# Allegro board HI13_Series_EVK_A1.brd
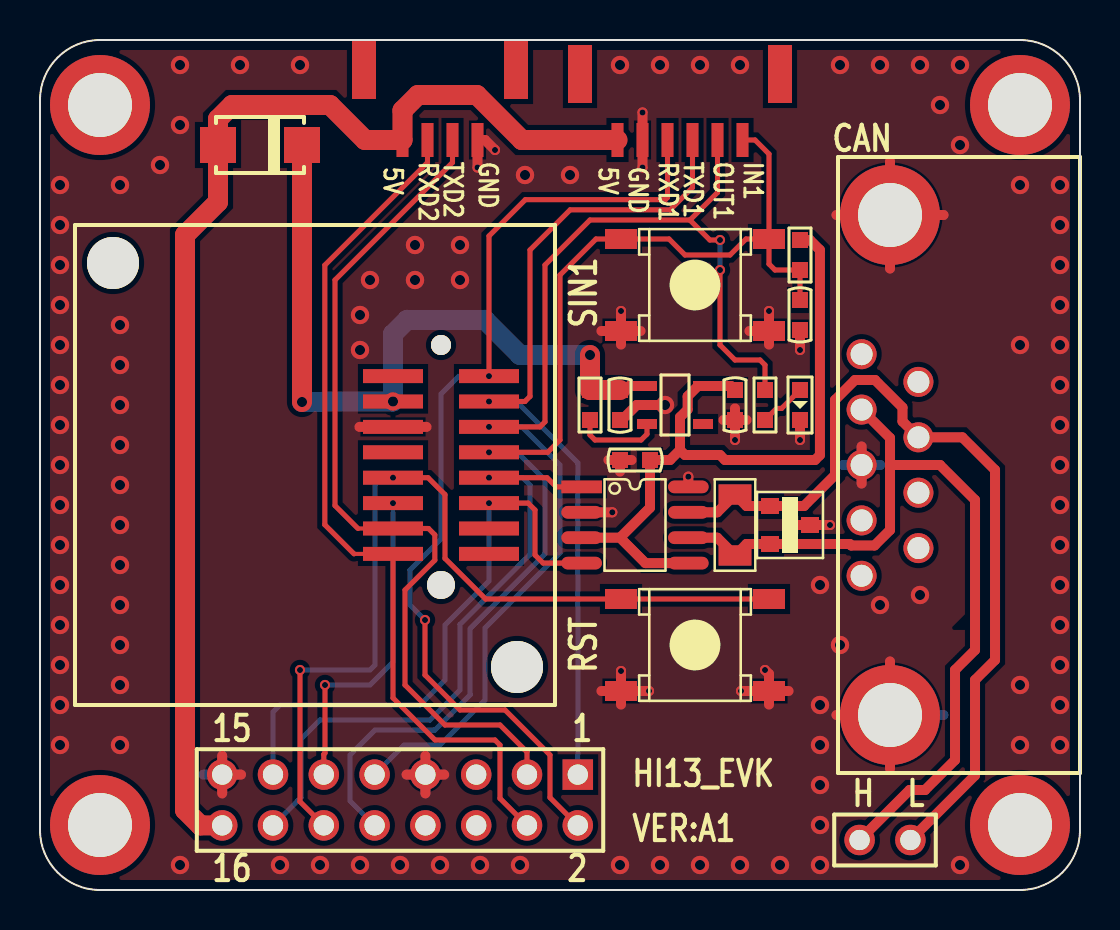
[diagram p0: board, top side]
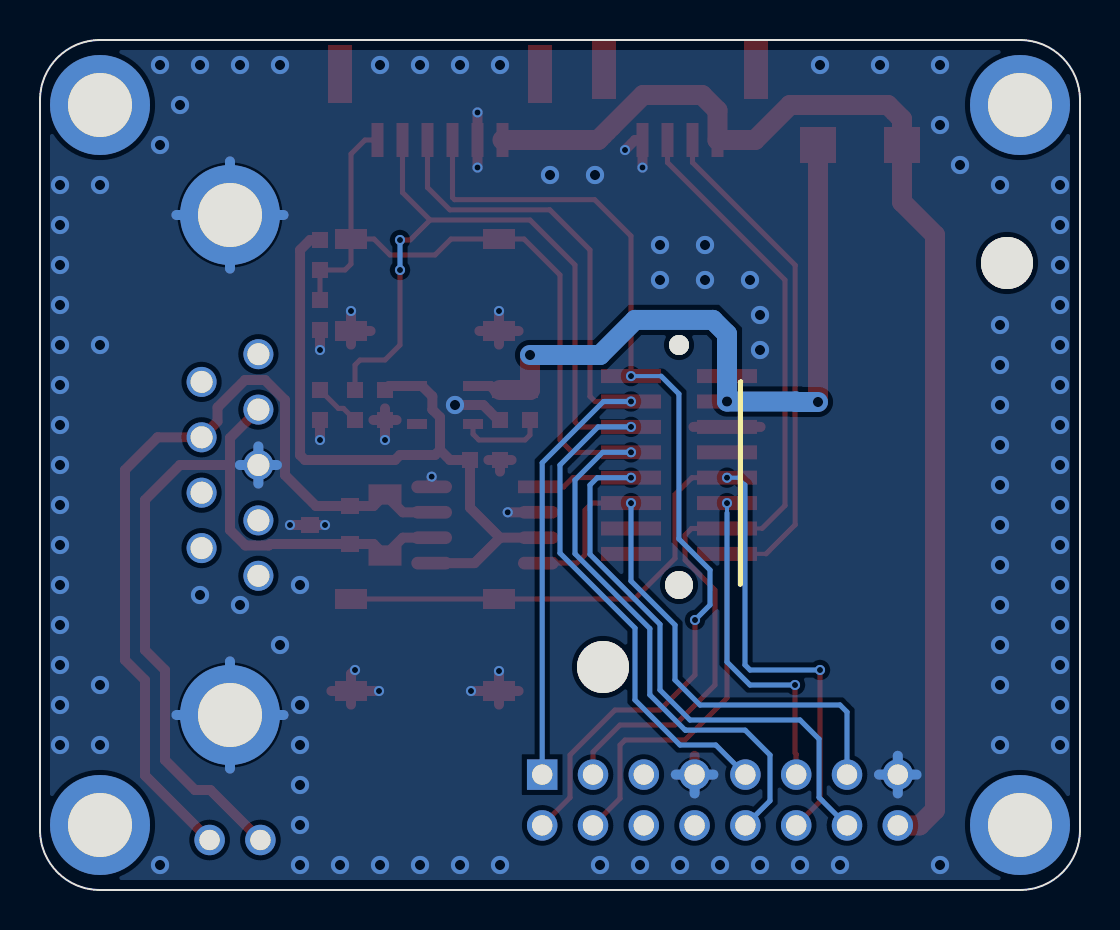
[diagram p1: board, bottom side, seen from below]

Outline 52 x 42.5 mm; copper layers: TOP, BOTTOM. Coordinates in mm from the lower left corner of the outline.
Outline path: 0,39.5 0,3 arc(0.88,0.88) 3,0 49,0 arc(51.12,0.88) 52,3 52,39.5 arc(51.12,41.62) 49,42.5 3,42.5 arc(0.88,41.62) 0,39.5

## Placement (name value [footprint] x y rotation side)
C1  0.1uF  [C0603]  29 24.25 270 top
C2  1uF  [C0603]  34.75 24.25 90 top
C3  0.1uF  [C0603]  38 28.75 90 top
C4  0.1uF  [C0603]  29.75 21.5 0 top
D1  1N4007  [DO-214AC]  11 37.25 180 top
D3  SM24CANB-02HTG  [SOT23-3-0_95]  37.5 18.25 270 top
D4  RED  [LED0603]  38 24.25 270 top
H1  HOLE  [HOLE-3-MM]  3 39.25 0 top
H2  HOLE  [HOLE-3-MM]  3 3.25 0 top
H3  HOLE  [HOLE-3-MM]  49 3.25 0 top
H4  HOLE  [HOLE-3-MM]  49 39.25 0 top
J1  CON6  [A1257WV-S-6P]  32 37.5 0 top
J2  CON4  [GH1X4-1_25MM_90]  20 37.5 0 top
J3  CONN PCB 8x2  [HEADER2X8-2_54MM]  18 4.5 180 top
J5  DB9  [DB9_FEMALE]  42.5 21.25 270 top
J6  CONN PCB 2  [HEADER1X2-2_54MM]  42.25 2.5 180 top
K1  Button2  [BUTTON_6X6]  32.75 12.25 270 top
K2  Button2  [BUTTON_6X6]  32.75 30.25 270 top
R1  4.7K  [R0603]  27.5 24.25 90 top
R2  4.7K  [R0603]  38 31.75 90 top
R3  120R  [R1206]  34.75 18.25 270 top
R5  510R  [R0603]  36.25 24.25 270 top
U1  RS3219-3.3YF5  [SOT23-5-0_95]  31.75 24.25 270 top
U2  SIT65HVD234DR  [SOP8]  29.75 18.25 0 top
U3  HI13  [HI13_UCX]  13.75 21.25 0 top

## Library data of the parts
C1-C4 = Capacity_Nonpolarity
D1 = diode
D3 = BAT54A/SOT
D4 = LED
H1-H4 = HOLE
J1 = CON6
J2 = CON4
J3 = CONN PCB 8x2
J5 = CONN_DB9M_MTGTABS
J6 = CONN PCB 2
K1 K2 = Button2
R1-R3 R5 = Res
U1 = XC6210
U2 = SN65HVD234-Q1
U3 = hi13

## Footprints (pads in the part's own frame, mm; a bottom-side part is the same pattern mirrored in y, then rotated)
A1257WV-S-6P
  rect 1.2x2.9 smd: (-5,3.3) (5,3.3)
  rect 0.6x1.7 smd: 1(-3.125,0) 2(-1.875,0) 3(-0.625,0) 4(0.625,0) 5(1.875,0) 6(3.125,0)
BUTTON_6X6
  rect 1x1.6 smd: 1(2.3,3.7) 2(2.3,-3.7) 3(-2.3,-3.7) 4(-2.3,3.7)
C0603
  rect 0.8x0.8 smd: 1(-0.75,0) 2(0.75,0)
DB9_FEMALE
  round 1.5 hole 1.1: 1(-5.54,-1.42) 2(-2.77,-1.42) 3(0,-1.42) 4(2.77,-1.42) 5(5.54,-1.42) 6(-4.155,1.42) 7(-1.385,1.42) 8(1.385,1.42) 9(4.155,1.42)
  round 5 hole 3.2: M1(12.5,0) M2(-12.5,0)
DO-214AC
  rect 1.8x1.8 smd: 1(2.1,0) 2(-2.1,0)
GH1X4-1_25MM_90
  rect 1.2x2.9 smd: (-3.8,3.5) (3.8,3.5)
  rect 0.6x1.7 smd: 1(-1.875,0) 2(-0.625,0) 3(0.625,0) 4(1.875,0)
HEADER1X2-2_54MM
  round 1.524 hole 1.016: 1(-1.27,0) 2(1.27,0)
HEADER2X8-2_54MM
  rect 1.524x1.524 hole 1.016: 1(-8.89,-1.27)
  round 1.524 hole 1.016: 2(-8.89,1.27) 3(-6.35,-1.27) 4(-6.35,1.27) 5(-3.81,-1.27) 6(-3.81,1.27) 7(-1.27,-1.27) 8(-1.27,1.27) 9(1.27,-1.27) 10(1.27,1.27) 11(3.81,-1.27) 12(3.81,1.27) 13(6.35,-1.27) 14(6.35,1.27) 15(8.89,-1.27) 16(8.89,1.27)
HI13_UCX
  round 2.6 hole 2.6 unplated: (-10.1,10.1) (10.1,-10.1)
  round 1 hole 1 unplated: (6.3,6)
  round 1.4 hole 1.4 unplated: (6.3,-6)
  rect 3x0.7 smd: 1(8.7,-4.445) 2(3.9,-4.445) 3(8.7,-3.175) 4(3.9,-3.175) 5(8.7,-1.905) 6(3.9,-1.905) 7(8.7,-0.635) 8(3.9,-0.635) 9(8.7,0.635) 10(3.9,0.635) 11(8.7,1.905) 12(3.9,1.905) 13(8.7,3.175) 14(3.9,3.175) 15(8.7,4.445) 16(3.9,4.445)
HOLE-3-MM
  round 5 hole 3.2: 1(0,0)
LED0603
  rect 0.8x0.8 smd: 1(-0.75,0) 2(0.75,0)
R0603
  rect 0.8x0.8 smd: 1(-0.75,0) 2(0.75,0)
R1206
  rect 1.016x1.651 smd: 1(-1.524,0) 2(1.524,0)
SOP8
  rect 2.032x0.635 smd: 1(-2.667,1.905)
  oval 2.032x0.635 smd: 2(-2.667,0.635) 3(-2.667,-0.635) 4(-2.667,-1.905) 5(2.667,-1.905) 6(2.667,-0.635) 7(2.667,0.635) 8(2.667,1.905)
SOT23-3-0_95
  rect 0.8x0.9 smd: 1(-0.95,-1) 2(0.95,-1) 3(0,1)
SOT23-5-0_95
  rect 0.5x1 smd: 1(-0.95,-1.4) 2(0,-1.4) 3(0.95,-1.4) 4(0.95,1.4) 5(-0.95,1.4)

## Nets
GND: C1.2 C2.1 C3.1 C4.1 D3.3 D4.2(-) J1.2 J2.4 J3.7(12) J3.15(16) J5.3 J5.M1 J5.M2 K1.1 K1.2 K2.1 K2.2 U1.2(VSS) U2.2(GND) U2.8(RS) U3.12(GND)
VCC: D1.1(P) J1.1 J2.1 J3.16(8)
CAN_RX: J3.13(15) U2.4(RXD) U3.5(CAN_RX)
CAN_TX: J3.14(7) U2.1(TXD) U3.7(CAN_TX)
CANH: D3.1 J5.7 J6.1 R3.1 U2.7(CAN-H)
CANL: D3.2 J5.2 J6.2 R3.2 U2.6(CAN-L)
DP3V3: C2.2 C4.2 R2.2 U1.5(VOUT) U2.3(VCC) U2.5(EN)
DP5V: C1.1 D1.2(N) R1.2 U1.1(VIN) U3.14(VDD)
IO5: J3.11(14) U3.6(IO5)
NRST: J3.12(6) K1.3 K1.4 U3.8(NRST)
RXD1: J1.3 J3.2(1) U3.15(RXD1)
RXD2: J2.2 J3.4(2) U3.2(RXD2)
SYNC_IN: C3.2 J1.6 J3.10(5) K2.3 K2.4 R2.1 U3.9(SYNC_IN1)
SYNC_OUT: J1.5 J3.9(13) R5.1 U3.11(SYNC_OUT1)
TXD1: J1.4 J3.1(9) U3.13(TXD1)
TXD2: J2.3 J3.3(10) U3.4(TXD2)
N1746824: D4.1(+) R5.2
N1748528: R1.1 U1.3(CE)

Pads without a net: H1 1; H2 1; H3 1; H4 1; J3 5 6 8; J5 1 4 5 6 8 9; U1 4; U3 1 3 10 16

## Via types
v1: diameter 0.508, hole 0.305, TOP to BOTTOM, 30 vias
v2: diameter 0.914, hole 0.508, TOP to BOTTOM, 97 vias

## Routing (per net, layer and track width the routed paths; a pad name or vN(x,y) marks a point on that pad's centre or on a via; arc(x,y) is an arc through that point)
GND: length 94.8
  TOP w0.5: v1(22.75,37) 22.25,37.5 J2.4 v1(21.88,36.12) ; 39.82,33.75 J5.M2 ; J5.M2 45.18,33.75 ; J5.M2 42.5,31.07 ; J5.M2 42.5,36.43 ; 41.08,22.18 J5.3 41.08,20.32 ; U2.8 v1(32.42,20.67) ; 42.5,6.07 J5.M1 ; J5.M1 39.82,8.75 ; J5.M1 42.5,11.43 ; 34.17,23.5 C2.1 ; C2.1 34.75,24.08 ; C2.1 v1(34.75,22.5) ; C2.1 35.33,23.5 ; U2.2 v1(28.62,18.88) ; v2(31.25,24.25) U1.2 29.84,24.25 29.09,23.5 C1.2 ; D4.2 v1(38,22.5) ; C3.1 v1(38,27) ; 28.42,21.5 C4.1 ; C4.1 29.58,21.5 ; C4.1 29,20.92 ; J3.15 10.05,5.77 ; J3.15 9.11,4.83 ; J3.15 9.11,6.71 ; 18.33,5.77 J3.7 ; J3.7 20.21,5.77 ; J3.7 19.27,6.71 ; J3.7 19.27,4.83 ; K1.1 v1(35.05,9.95) ; K1.1 36.45,10.8 v1(36.25,11) ; K1.1 36.45,9.27 ; K1.1 37.43,9.95 ; 29.05,9.27 K1.2 ; K1.2 v1(30.45,9.95) ; K1.2 28.07,9.95 ; K1.2 v1(29.05,10.95) ; 15.97,23.16 U3.12 19.33,23.16 ; K2.1 v1(36.45,28.95) ; K2.1 36.45,27.27 ; K2.1 35.47,27.95 ; K2.2 v1(29.05,28.95) ; K2.2 30.03,27.95 ; K2.2 28.07,27.95 ; K2.2 29.05,27.27 ; v1(39.5,18.25) D3.3 v1(37.75,18.25) ; v1(30.12,36.12) J1.2 v1(30.12,38.88)
  BOTTOM w0.5: J5.3 42.01,21.25 ; J5.3 41.08,20.32 ; J5.3 40.15,21.25 ; J5.3 41.08,22.18 ; 9.11,4.83 J3.15 ; J3.15 8.17,5.77 ; J3.15 9.11,6.71 ; J3.15 10.05,5.77 ; 39.82,8.75 J5.M1 ; J5.M1 42.5,11.43 ; J5.M1 42.5,6.07 ; J5.M1 45.18,8.75 ; 19.27,4.83 J3.7 ; J3.7 20.21,5.77 ; J3.7 18.33,5.77 ; J5.M2 42.5,36.43 ; J5.M2 42.5,31.07 ; J5.M2 45.18,33.75 ; J5.M2 39.82,33.75
  vias: v2(1,35.25) v2(1,33.25) v2(1,31.25) v2(1,29.25) v2(1,27.25) v2(1,25.25) v2(1,23.25) v2(1,21.25) v2(1,19.25) v2(1,17.25) v2(1,15.25) v2(1,13.25) v2(1,11.25) v2(1,9.25) v2(1,7.25) v2(4,35.25) v2(4,28.25) v2(4,26.25) v2(4,24.25) v2(4,22.25) v2(4,20.25) v2(4,18.25) v2(4,16.25) v2(4,14.25) v2(4,12.25) v2(4,10.25) v2(4,7.25) v2(6,36.25) v2(7,41.25) v2(7,38.25) v2(7,1.25) v2(10,41.25) v2(12,1.25) v2(13,41.25) v2(14,1.25) v2(16,28.75) v2(16,27) v2(16,1.25) v2(16.5,30.5) v2(18,1.25) v2(18.75,32.25) v2(18.75,30.5) v2(20,1.25) v2(21,32.25) v2(21,30.5) v2(22,1.25) v2(24,1.25) v2(24.25,35.75) v2(26.5,35.75) v2(29,41.25) v2(29,1.25) v2(31,41.25) v2(31,1.25) v2(33,41.25) v2(33,1.25) v2(35,41.25) v2(35,1.25) v2(37,1.25) v2(39,15.25) v2(39,9.25) v2(39,7.25) v2(39,5.25) v2(39,3.25) v2(39,1.25) v2(40,41.25) v2(40,12.25) v2(42,41.25) v2(42,14.25) v2(44,41.25) v2(44,14.75) v2(45,39.25) v2(46,41.25) v2(46,37.25) v2(46,1.25) v2(49,35.25) v2(49,27.25) v2(49,10.25) v2(49,7.25) v2(51,35.25) v2(51,33.25) v2(51,31.25) v2(51,29.25) v2(51,27.25) v2(51,25.25) v2(51,23.25) v2(51,21.25) v2(51,19.25) v2(51,17.25) v2(51,15.25) v2(51,13.25) v2(51,11.25) v2(51,9.25) v2(51,7.25)
VCC: length 61.1
  TOP w1: J3.16 8.02,3.23 7.25,4 7.25,32.75 8.9,34.4 D1.1 8.9,38.54 9.61,39.25 14.5,39.25 16.25,37.5 J2.1 18.12,38.98 18.9,39.75 21.84,39.75 24.09,37.5 J1.1
CAN_RX: length 29.3
  TOP w0.254: U2.4 25.16,16.34 24.75,16.75 24.75,19 24.41,19.34 v1(22.45,19.34)
  BOTTOM w0.254: v1(22.45,19.34) 22.45,15.45 20.25,13.25 20.25,10.5 19,9.25 12,9.25 11.65,8.9 J3.13
CAN_TX: length 32.6
  TOP w0.254: U2.1 25.81,20.16 25.35,20.61 v1(22.45,20.61)
  BOTTOM w0.254: v1(22.45,20.61) 24.14,20.61 24.5,20.25 24.5,16.78 21,13.28 21,10 19.5,8.5 14,8.5 13.05,7.55 13.05,4.63 J3.14
CANH: length 43.3
  TOP w0.5: U2.7 33.86,18.88 R3.1 35.32,19.2 D3.1 38.2,19.2 39.75,20.75 39.75,24.5 40.75,25.5 41.75,25.5 43.12,24.13 43.12,23.43 J5.7 46.12,22.64 47.75,21 47.75,11.5 46.75,10.5 46.75,5.73 J6.1
CANL: length 42.5
  TOP w0.5: 42.5,21.25 45,21.25 46.75,19.5 46.75,12 45.75,11 45.75,6.5 44.25,5 43.48,5 J6.2 ; 42.5,21.25 42.5,18 41.73,17.23 40.56,17.23 40.49,17.3 D3.2 35.32,17.3 R3.2 33.86,17.62 U2.6 ; 42.5,21.25 42.5,22.6 J5.2
DP3V3: length 36.3
  TOP w0.5: 29,17.62 30.27,16.34 U2.5 ; 29,17.62 30.5,19.12 C4.2 31.5,21.5 32,22 ; 29,17.62 U2.3 ; 32,22 32.25,21.75 34,21.75 34.25,21.5 38.75,21.5 39,21.75 39,32 38.5,32.5 R2.2 ; 32,22 32,23.64 32.38,24.02 32.38,24.68 32.9,25.2 U1.5 34.55,25.2 C2.2
DP5V: length 36.3
  TOP w0.5: U1.1 29.47,25.2 29.27,25 C1.1
  TOP w1: C1.1 R1.2 v2(27.5,26.75) ; D1.2 v2(13.1,24.4)
  BOTTOM w1: v2(27.5,26.75) 24,26.75 22.25,28.5 18.36,28.5 17.65,27.8 v2(17.65,24.43) 14.21,24.43 14.18,24.4 v2(13.1,24.4)
IO5: length 16.3
  TOP w0.254: J3.11 14.19,6.79 14.25,6.85 v1(14.25,10.25)
  BOTTOM w0.203: 17.65,18.85 v1(17.65,19.34)
  BOTTOM w0.254: 17.65,18.85 17.65,11.4 16.5,10.25 v1(14.25,10.25)
NRST: length 45.3
  TOP w0.254: J3.12 13,4.42 v1(13,11) ; v1(17.65,20.61) 19.4,20.61 20.25,19.77 20.25,16.58 22.28,14.55 K1.3 K1.4
  BOTTOM w0.203: 16.75,20.25 17.12,20.61 v1(17.65,20.61)
  BOTTOM w0.254: v1(13,11) 16.5,11 16.75,11.25 16.75,20.25
RXD1: length 49.4
  TOP w0.254: v1(19.25,13.5) 19.25,10.75 21,9 23.25,9 25.5,6.75 25.5,4.62 J3.2 ; v1(22.45,25.7) 22.45,32.7 24.27,34.52 31.27,34.52 31.38,34.62 J1.3
  BOTTOM w0.203: v1(22.45,25.7) 20.95,25.7
  BOTTOM w0.254: 20.95,25.7 20.05,24.8 20.05,17.55 18.5,16 18.5,14.25 v1(19.25,13.5)
RXD2: length 43.5
  TOP w0.203: U3.2 15.7,16.8
  TOP w0.254: J2.2 19.38,36.38 14.24,31.24 14.24,18.26 15.7,16.8 ; J3.4 23,4.58 23,7.25 22.75,7.5 19.75,7.5 17.65,9.6 U3.2
SYNC_IN: length 61.2
  TOP w0.254: v1(22.45,21.89) 25.39,21.89 26,22.5 26,30.75 27.8,32.55 K2.3 31.45,32.55 32.25,31.75 34.5,31.75 35.3,32.55 K2.4 ; K2.4 36.45,36.8 35.75,37.5 J1.6 ; K2.4 36.45,31.3 36.75,31 R2.1 C3.2
  BOTTOM w0.254: J3.10 15.5,4.46 15.5,6.75 16.74,7.99 19.71,7.99 19.72,8 19.75,8 21.51,9.76 21.51,13.07 25.25,16.81 25.25,20.5 23.87,21.89 v1(22.45,21.89)
SYNC_OUT: length 59.3
  TOP w0.254: v1(22.45,23.16) 25,23.16 25.25,23.41 25.25,31.25 27.5,33.5 32.5,33.5 ; v1(34,32.5) 33.49,32.5 32.5,33.49 32.5,33.5 ; v1(34,31) 34,27.25 34.75,26.5 36,26.5 36.25,26.25 R5.1 ; 32.5,33.5 33.88,34.88 J1.5
  BOTTOM w0.254: v1(22.45,23.16) 24.09,23.16 26,21.25 26,16.84 22.25,13.09 22.25,9.5 20,7.25 18.21,7.25 J3.9 ; v1(34,31) v1(34,32.5)
TXD1: length 42.6
  TOP w0.254: v1(22.45,24.43) 24.25,24.43 24.5,24.68 24.5,32 26.51,34.01 31.51,34.01 32.62,35.12 J1.4
  BOTTOM w0.254: v1(22.45,24.43) 23.82,24.43 26.89,21.36 J3.1
TXD2: length 43.1
  TOP w0.203: U3.4 15.9,18.07
  TOP w0.254: J2.3 20.62,36.38 14.75,30.5 14.75,19.22 15.9,18.07 ; U3.4 19.43,18.07 19.74,17.76 19.74,16.49 18.25,15 18.25,10.25 20.25,8.25 23,8.25 24.35,6.9 J3.3
N1746824: length 2.4
  TOP w0.254: D4.1 37.08,24.08 36.83,24.08 R5.2
N1748528: length 4.3
  TOP w0.254: R1.1 27.5,22.75 27.75,22.5 30.05,22.5 30.35,22.8 U1.3

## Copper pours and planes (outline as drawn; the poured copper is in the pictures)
GND on TOP: 3,0.5 0.5,3 0.5,39.5 3,42 49.25,42 51.5,39.75 51.5,3 49,0.5 ; 16 cut-outs
GND on BOTTOM: 3,0.5 0.5,3 0.5,39.5 3,42 49.25,42 51.5,39.75 51.5,3 49,0.5 ; 4 cut-outs

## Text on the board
Ref Des/Silkscreen Top: 5V | RXD2 | TXD2 | GND | RXD1 | TXD1 | OUT1 | IN1 | 15 | 16 | 2 | 1 | HI13_EVK | VER:A1 | CAN | H | L | SIN1 | RST
COMPVAL_TYPE_TOP: FIGURE | SIZE | 12.0 | 20.0 | 21.654 | 40.0 | 86.61 | 141.732 | 59.055x23.622 | 70.866x23.622 | DRILL CHART: TOP to BOTTOM | ALL UNITS ARE IN MILS | PLATED | NON-PLATED | QTY | 47 | 3 | 28 | 32 | 4 | 1 | 2
